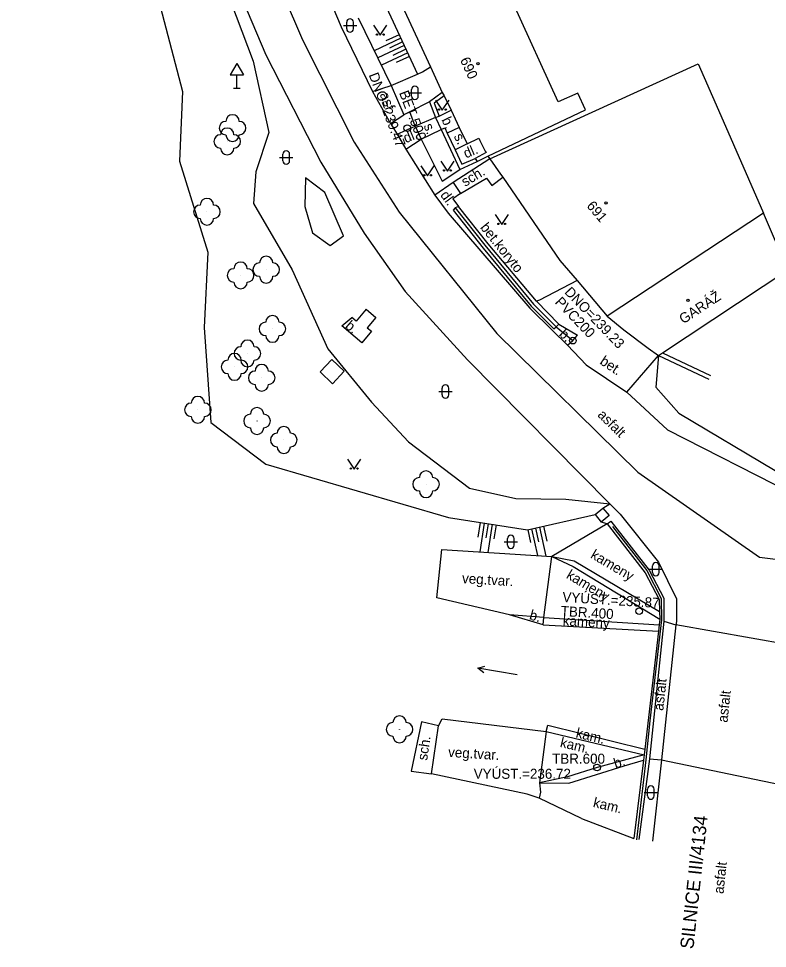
# Model space of a CAD drawing. Extents: x -621335 to -621199, y -1175437 to -1175180.
# Drawn here: x -621295.5 to -621239.4, y -1175437.3 to -1175367.7 of the extents above; entities that cross this region are included whole.
import ezdxf

# ---------------------------------------------------------------- set-up
doc = ezdxf.new("R2010")
doc.units = 0
for name, color, linetype in [('Budovy - měřené', 7, 'Continuous'), ('Budovy - zadní trakty', 7, 'Continuous'), ('Doplňkové značky', 7, 'Continuous'), ('Názvy', 7, 'Continuous'), ('Pomocné popisy', 7, 'Continuous'), ('Rozhraní ploch', 7, 'Continuous'), ('Výškopis', 7, 'Continuous'), ('Zeleň', 7, 'Continuous'), ('Značky druhů budov', 7, 'Continuous'), ('Značky kultur', 7, 'Continuous'), ('Čísla popisná_evidenční', 7, 'Continuous')]:
    doc.layers.add(name, color=color, linetype=linetype)

msp = doc.modelspace()

# ---------------------------------------------------------------- linework, layer by layer
at = {"layer": 'Budovy - měřené'}
for p, q in [((-621251.4, -1175389.96), (-621250.14, -1175390.99)), ((-621248.33, -1175392.36), (-621247.56, -1175392.9))]:
    msp.add_line(p, q, dxfattribs=at)
for points in [[(-621262.49, -1175364.79), (-621266.74, -1175366.77), (-621264.62, -1175371.33)], [(-621263.73, -1175373.23), (-621263.6, -1175373.49), (-621263.08, -1175374.57), (-621262.46, -1175375.85), (-621261.86, -1175377.08), (-621260.99, -1175376.66), (-621260.92, -1175376.82)], [(-621260.52, -1175377.63), (-621260.46, -1175377.74), (-621261.26, -1175378.17), (-621261.13, -1175378.41), (-621260.32, -1175378)], [(-621259.38, -1175379.34), (-621259.21, -1175379.58), (-621254.93, -1175385.81), (-621253.64, -1175387.3), (-621251.4, -1175389.96)]]:
    msp.add_lwpolyline(points, dxfattribs=at)
at = {"layer": 'Budovy - zadní trakty'}
for points in [[(-621260.32, -1175378), (-621253.01, -1175374.55), (-621253.59, -1175373.29), (-621255.05, -1175373.95), (-621258.42, -1175366.56), (-621254.88, -1175364.95), (-621256.13, -1175362.49), (-621257.55, -1175362.98)], [(-621260.17, -1175378.21), (-621244.57, -1175371.1), (-621243.06, -1175374.57), (-621239.7, -1175382.27), (-621251.4, -1175389.96)], [(-621247.56, -1175392.9), (-621247.26, -1175392.7), (-621237.86, -1175386.5), (-621239.7, -1175382.27)]]:
    msp.add_lwpolyline(points, dxfattribs=at)
at = {"layer": 'Doplňkové značky'}
for p, q in [((-621279.11, -1175371.064), (-621279.61, -1175371.93)), ((-621279.11, -1175371.064), (-621278.61, -1175371.93)), ((-621264.62, -1175371.33), (-621263.73, -1175373.23)), ((-621279.61, -1175371.93), (-621278.61, -1175371.93)), ((-621279.11, -1175372.93), (-621279.11, -1175371.93)), ((-621279.36, -1175372.93), (-621278.86, -1175372.93)), ((-621264.25, -1175375.11), (-621265.77, -1175375.75)), ((-621264.25, -1175375.11), (-621263.97, -1175375)), ((-621264.25, -1175375.11), (-621263.82, -1175376.02)), ((-621265.77, -1175375.75), (-621265.31, -1175376.74)), ((-621265.31, -1175376.74), (-621263.82, -1175376.02)), ((-621263.82, -1175376.02), (-621263.55, -1175375.89)), ((-621260.92, -1175376.82), (-621260.52, -1175377.63)), ((-621260.32, -1175378), (-621260.17, -1175378.21)), ((-621260.17, -1175378.21), (-621262.93, -1175379.98)), ((-621260.17, -1175378.21), (-621259.38, -1175379.34)), ((-621262.93, -1175379.98), (-621262.36, -1175380.8)), ((-621250.14, -1175390.99), (-621248.33, -1175392.36)), ((-621247.26, -1175392.7), (-621243.65, -1175394.41)), ((-621247.56, -1175392.9), (-621247.75, -1175395.27)), ((-621247.56, -1175392.9), (-621243.78, -1175394.68)), ((-621265.29, -1175420.31), (-621266.06, -1175424)), ((-621264.01, -1175420.6), (-621265.29, -1175420.31)), ((-621264.54, -1175424.19), (-621264.01, -1175420.6)), ((-621266.06, -1175424), (-621264.54, -1175424.19))]:
    msp.add_line(p, q, dxfattribs=at)
for points in [[(-621267.55, -1175372.72), (-621265.59, -1175371.86), (-621265.22, -1175371.69), (-621264.62, -1175371.33)], [(-621263.73, -1175373.23), (-621264.69, -1175373.95), (-621264.25, -1175375.11)], [(-621264.69, -1175373.95), (-621266.17, -1175374.7), (-621266.6, -1175374.92)], [(-621263.6, -1175373.49), (-621264.33, -1175374.05), (-621263.97, -1175375)], [(-621263.82, -1175376.02), (-621262.42, -1175378.99), (-621261.13, -1175378.41)], [(-621263.55, -1175375.89), (-621263.36, -1175376.28), (-621262.78, -1175377.52), (-621262.27, -1175378.6), (-621261.26, -1175378.17)], [(-621265.31, -1175376.74), (-621263.73, -1175379.88), (-621262.42, -1175378.99)], [(-621262.36, -1175380.8), (-621260.43, -1175379.64), (-621260.03, -1175380.2), (-621259.21, -1175379.58)], [(-621253.64, -1175387.3), (-621256.46, -1175388.77), (-621256.67, -1175388.86)], [(-621251.39, -1175405.51), (-621248.55, -1175409.16), (-621247.51, -1175411.16), (-621247.47, -1175412.05), (-621247.45, -1175412.62), (-621247.5, -1175413.05), (-621247.55, -1175413.54), (-621248.58, -1175422.36), (-621248.63, -1175422.77), (-621248.68, -1175423.17), (-621249.4, -1175429.04)], [(-621251.11, -1175405.3), (-621248.25, -1175408.97), (-621247.16, -1175411.07), (-621247.15, -1175412.79), (-621248.22, -1175423.07), (-621249.01, -1175429.11)], [(-621251, -1175405.71), (-621248.41, -1175408.99), (-621247.36, -1175411.08), (-621247.33, -1175412.67), (-621248.19, -1175420.23), (-621248.49, -1175423.16), (-621249.19, -1175429.13)], [(-621255.54, -1175407.94), (-621253.94, -1175408.7), (-621247.45, -1175412.62)], [(-621248.63, -1175422.77), (-621252.15, -1175423.72), (-621254.36, -1175424.41), (-621256.46, -1175424.88)], [(-621253.31, -1175427.55), (-621256.49, -1175426.01), (-621257.38, -1175425.72), (-621264.54, -1175424.19)]]:
    msp.add_lwpolyline(points, dxfattribs=at)
for centre, radius in [((-621266.351, -1175375.91), 0.25), ((-621266.351, -1175375.91), 0.0005), ((-621253.961, -1175391.8), 0.25), ((-621253.961, -1175391.8), 0.0005), ((-621248.99, -1175412.03), 0.25), ((-621248.99, -1175412.03), 0.0005), ((-621252.15, -1175423.72), 0.25), ((-621252.15, -1175423.72), 0.0005)]:
    msp.add_circle(centre, radius, dxfattribs=at)
at = {"layer": 'Rozhraní ploch'}
for p, q in [((-621268.96, -1175373.16), (-621267.55, -1175372.72)), ((-621268.96, -1175373.16), (-621267.61, -1175375.57)), ((-621267.55, -1175372.72), (-621266.6, -1175374.92)), ((-621263.97, -1175375), (-621263.08, -1175374.57)), ((-621267.61, -1175375.57), (-621266.6, -1175374.92)), ((-621267.61, -1175375.57), (-621267.12, -1175376.35)), ((-621267.12, -1175376.35), (-621265.77, -1175375.75)), ((-621262.46, -1175375.85), (-621263.36, -1175376.28)), ((-621267.12, -1175376.35), (-621266.47, -1175377.49)), ((-621266.47, -1175377.49), (-621265.31, -1175376.74)), ((-621261.86, -1175377.08), (-621262.78, -1175377.52)), ((-621266.47, -1175377.49), (-621264.29, -1175380.91)), ((-621262.93, -1175379.98), (-621264.29, -1175380.91)), ((-621255.02, -1175390.58), (-621253.6, -1175391.4)), ((-621255.49, -1175391.04), (-621254.36, -1175392.15)), ((-621255.2, -1175390.78), (-621253.96, -1175391.8)), ((-621249.92, -1175395.65), (-621247.56, -1175392.9)), ((-621252.29, -1175404.81), (-621251.71, -1175404.33)), ((-621251.71, -1175404.33), (-621251.25, -1175404.89)), ((-621252.29, -1175404.81), (-621251.83, -1175405.37)), ((-621251.25, -1175404.89), (-621251.83, -1175405.37)), ((-621251.39, -1175405.51), (-621255.54, -1175407.94)), ((-621251.39, -1175405.51), (-621251.11, -1175405.3)), ((-621256.12, -1175412.51), (-621255.54, -1175407.94)), ((-621258.69, -1175412.31), (-621264.15, -1175411.04)), ((-621256.17, -1175413.05), (-621258.69, -1175412.31)), ((-621256.12, -1175412.51), (-621258.69, -1175412.31)), ((-621256.17, -1175413.05), (-621256.12, -1175412.51)), ((-621256.12, -1175412.51), (-621247.5, -1175413.05)), ((-621247.15, -1175412.79), (-621246.24, -1175413.05)), ((-621256.17, -1175413.05), (-621247.55, -1175413.54)), ((-621246.24, -1175413.05), (-621247.33, -1175423.15)), ((-621237.16, -1175414.66), (-621246.24, -1175413.05)), ((-621264.01, -1175420.6), (-621263.75, -1175420.09)), ((-621263.75, -1175420.09), (-621255.95, -1175421.04)), ((-621255.95, -1175421.04), (-621255.82, -1175420.55)), ((-621255.82, -1175420.55), (-621248.58, -1175422.36)), ((-621255.95, -1175421.04), (-621256.46, -1175424.88)), ((-621255.95, -1175421.04), (-621248.63, -1175422.77)), ((-621248.22, -1175423.07), (-621247.33, -1175423.15)), ((-621247.33, -1175423.15), (-621238.43, -1175424.99)), ((-621253.31, -1175427.55), (-621249.4, -1175429.04))]:
    msp.add_line(p, q, dxfattribs=at)
for points in [[(-621289.26, -1175328.38), (-621284.69, -1175342.49), (-621282.48, -1175348.71), (-621278.54, -1175359.18), (-621274.2, -1175369.3), (-621270.32, -1175376.95), (-621266.97, -1175382.2), (-621259.66, -1175391.26), (-621249.09, -1175401.63), (-621240, -1175407.99), (-621230.92, -1175409.11)], [(-621275.68, -1175358), (-621271.3, -1175368.33), (-621268.96, -1175373.16)], [(-621281.22, -1175360.35), (-621276.93, -1175370.43), (-621272.83, -1175378.46)], [(-621272.83, -1175378.46), (-621269.57, -1175383.76), (-621266.5, -1175388.12), (-621261.85, -1175393.23), (-621251.2, -1175404)], [(-621264.29, -1175380.91), (-621263.29, -1175382.27), (-621257.18, -1175389.37), (-621255.49, -1175391.04)], [(-621262.36, -1175380.8), (-621262.95, -1175381.19), (-621262.53, -1175381.76)], [(-621262.53, -1175381.76), (-621262.76, -1175381.88), (-621262.92, -1175382.05)], [(-621262.92, -1175382.05), (-621260.67, -1175384.88), (-621257.08, -1175389.22), (-621255.39, -1175390.92)], [(-621262.76, -1175381.88), (-621260.54, -1175384.67), (-621256.9, -1175389.08), (-621255.2, -1175390.78)], [(-621255.02, -1175390.58), (-621256.67, -1175388.86), (-621260.3, -1175384.57), (-621262.53, -1175381.76)], [(-621269.44, -1175389.45), (-621268.71, -1175390.06), (-621269.35, -1175390.83), (-621269.03, -1175391.08), (-621269.75, -1175391.97), (-621271.26, -1175390.69), (-621270.5, -1175390.07)], [(-621269.44, -1175389.45), (-621270.18, -1175390.34), (-621270.5, -1175390.07)], [(-621255.39, -1175390.92), (-621255.2, -1175390.78), (-621255.02, -1175390.58)], [(-621254.36, -1175392.15), (-621253.96, -1175391.8), (-621253.6, -1175391.4)], [(-621254.36, -1175392.15), (-621252.96, -1175393.61), (-621249.92, -1175395.65)], [(-621271.09, -1175394.09), (-621272, -1175393.22), (-621272.88, -1175394.14)], [(-621272.88, -1175394.14), (-621271.95, -1175395.03), (-621271.09, -1175394.09)], [(-621249.92, -1175395.65), (-621246.88, -1175398.47), (-621237.56, -1175403.21), (-621230.15, -1175405.43)], [(-621251.2, -1175404), (-621250.43, -1175404.77), (-621247.54, -1175408.37), (-621246.2, -1175411.11), (-621246.21, -1175412.75), (-621246.226, -1175412.969), (-621246.234, -1175413.051)], [(-621264.15, -1175411.04), (-621263.76, -1175407.43), (-621255.54, -1175407.94)], [(-621255.54, -1175407.94), (-621253.87, -1175408.26), (-621247.47, -1175412.05)], [(-621256.46, -1175424.88), (-621254.27, -1175424.89), (-621250.12, -1175423.6), (-621248.68, -1175423.17)], [(-621247.33, -1175423.15), (-621247.99, -1175429.24)], [(-621256.46, -1175424.88), (-621256.38, -1175425.57), (-621256.49, -1175426.01)]]:
    msp.add_lwpolyline(points, dxfattribs=at)
at = {"layer": 'Výškopis'}
for p, q in [((-621270.02, -1175367.66), (-621267.55, -1175372.72)), ((-621266.956, -1175368.919), (-621267.954, -1175369.383)), ((-621266.83, -1175369.191), (-621268.821, -1175370.116)), ((-621266.577, -1175369.736), (-621268.558, -1175370.656)), ((-621266.703, -1175369.463), (-621267.696, -1175369.925)), ((-621266.324, -1175370.28), (-621268.294, -1175371.195)), ((-621266.451, -1175370.008), (-621267.438, -1175370.466)), ((-621266.198, -1175370.552), (-621267.18, -1175371.008)), ((-621260.896, -1175405.4), (-621261.065, -1175406.493)), ((-621260.599, -1175405.446), (-621260.934, -1175407.605)), ((-621260.303, -1175405.492), (-621260.468, -1175406.558)), ((-621260.006, -1175405.538), (-621260.333, -1175407.643)), ((-621259.71, -1175405.584), (-621259.871, -1175406.623)), ((-621257.338, -1175405.947), (-621257.124, -1175406.901)), ((-621257.046, -1175405.881), (-621256.597, -1175407.874)), ((-621256.753, -1175405.816), (-621256.519, -1175406.855)), ((-621256.46, -1175405.75), (-621255.973, -1175407.913)), ((-621256.168, -1175405.684), (-621255.914, -1175406.808)), ((-621251.39, -1175405.51), (-621251.83, -1175405.37))]:
    msp.add_line(p, q, dxfattribs=at)
for points in [[(-621295.45, -1175349.87), (-621290.21, -1175351.04), (-621287.51, -1175351.48), (-621286.52, -1175352.52), (-621286.18, -1175357.56), (-621285.26, -1175365.24), (-621283.18, -1175373.16), (-621283.4, -1175378.38)], [(-621268.17, -1175366.18), (-621268.08, -1175366.5), (-621265.59, -1175371.86)], [(-621283.4, -1175378.38), (-621281.29, -1175385.19), (-621281.56, -1175390.81), (-621281.06, -1175397.92), (-621276.95, -1175401.05), (-621263.28, -1175405.03), (-621257.35, -1175405.95), (-621252.29, -1175404.81)]]:
    msp.add_lwpolyline(points, dxfattribs=at)
at = {"layer": 'Zeleň'}
for p, q in [((-621265.77, -1175375.75), (-621266.17, -1175374.7)), ((-621251.71, -1175404.33), (-621251.2, -1175404))]:
    msp.add_line(p, q, dxfattribs=at)
for points in [[(-621281.79, -1175360.58), (-621277.88, -1175370.89), (-621276.71, -1175376.23)], [(-621276.71, -1175376.23), (-621277.69, -1175379.17), (-621277.86, -1175381.54), (-621274.98, -1175386.51), (-621272.3, -1175392.41), (-621269.04, -1175396.39), (-621266.25, -1175399.37), (-621261.69, -1175402.83), (-621258.22, -1175403.61), (-621254.48, -1175403.65), (-621251.2, -1175404)], [(-621273.97, -1175379.62), (-621274.02, -1175381.76), (-621273.45, -1175383.74), (-621272.13, -1175384.68), (-621271.12, -1175383.95), (-621272.52, -1175380.73), (-621273.97, -1175379.62)], [(-621247.75, -1175395.27), (-621246.03, -1175397.22), (-621238.82, -1175401.51)]]:
    msp.add_lwpolyline(points, dxfattribs=at)
for centre in [(-621279.43, -1175375.9), (-621279.83, -1175376.9), (-621281.35, -1175382.16), (-621276.91, -1175386.49), (-621278.83, -1175386.92), (-621276.45, -1175390.92), (-621278.32, -1175392.76), (-621279.28, -1175393.76), (-621277.25, -1175394.58), (-621282.03, -1175396.97), (-621277.6, -1175397.81), (-621275.6, -1175399.23), (-621264.95, -1175402.54), (-621266.93, -1175420.87)]:
    msp.add_circle(centre, 0.0005, dxfattribs=at)
for centre, start, end in [((-621279.43, -1175375.4), 0, 179.99999), ((-621279.93, -1175375.9), 89.99999, 269.99999), ((-621279.83, -1175376.4), 0, 179.99999), ((-621278.93, -1175375.9), 270, 89.99999), ((-621280.33, -1175376.9), 89.99999, 269.99999), ((-621279.43, -1175376.4), 179.99999, 359.99999), ((-621279.33, -1175376.9), 270, 89.99999), ((-621279.83, -1175377.4), 179.99999, 359.99999), ((-621281.35, -1175381.66), 0, 179.99999), ((-621281.85, -1175382.16), 89.99999, 269.99999), ((-621280.85, -1175382.16), 270, 89.99999), ((-621281.35, -1175382.66), 179.99999, 359.99999), ((-621276.91, -1175385.99), 0, 179.99999), ((-621279.33, -1175386.92), 89.99999, 269.99999), ((-621278.83, -1175386.42), 0, 179.99999), ((-621278.33, -1175386.92), 270, 89.99999), ((-621277.41, -1175386.49), 89.99999, 269.99999), ((-621276.41, -1175386.49), 270, 89.99999), ((-621276.91, -1175386.99), 179.99999, 359.99999), ((-621278.83, -1175387.42), 179.99999, 359.99999), ((-621276.45, -1175390.42), 0, 179.99999), ((-621276.95, -1175390.92), 89.99999, 269.99999), ((-621275.95, -1175390.92), 270, 89.99999), ((-621278.32, -1175392.26), 0, 179.99999), ((-621276.45, -1175391.42), 179.99999, 359.99999), ((-621279.28, -1175393.26), 0, 179.99999), ((-621278.82, -1175392.76), 89.99999, 269.99999), ((-621277.82, -1175392.76), 270, 89.99999), ((-621279.78, -1175393.76), 89.99999, 269.99999), ((-621278.32, -1175393.26), 179.99999, 359.99999), ((-621278.78, -1175393.76), 270, 89.99999), ((-621277.75, -1175394.58), 89.99999, 269.99999), ((-621277.25, -1175394.08), 0, 179.99999), ((-621276.75, -1175394.58), 270, 89.99999), ((-621279.28, -1175394.26), 179.99999, 359.99999), ((-621277.25, -1175395.08), 179.99999, 359.99999), ((-621282.03, -1175396.47), 0, 179.99999), ((-621282.53, -1175396.97), 89.99999, 269.99999), ((-621281.53, -1175396.97), 270, 89.99999), ((-621277.6, -1175397.31), 0, 179.99999), ((-621282.03, -1175397.47), 179.99999, 359.99999), ((-621278.1, -1175397.81), 89.99999, 269.99999), ((-621277.1, -1175397.81), 270, 89.99999), ((-621277.6, -1175398.31), 179.99999, 359.99999), ((-621275.6, -1175398.73), 0, 179.99999), ((-621276.1, -1175399.23), 89.99999, 269.99999), ((-621275.1, -1175399.23), 270, 89.99999), ((-621275.6, -1175399.73), 179.99999, 359.99999), ((-621264.95, -1175402.04), 0, 179.99999), ((-621265.45, -1175402.54), 89.99999, 269.99999), ((-621264.45, -1175402.54), 270, 89.99999), ((-621264.95, -1175403.04), 179.99999, 359.99999), ((-621266.93, -1175420.37), 0, 179.99999), ((-621267.43, -1175420.87), 89.99999, 269.99999), ((-621266.43, -1175420.87), 270, 89.99999), ((-621266.93, -1175421.37), 179.99999, 359.99999)]:
    msp.add_arc(centre, 0.5, start, end, dxfattribs=at)
at = {"layer": 'Značky druhů budov'}
for centre in [(-621261.06, -1175371.08), (-621251.47, -1175381.5), (-621245.35, -1175388.79)]:
    msp.add_circle(centre, 0.0875, dxfattribs=at)
at = {"layer": 'Značky kultur'}
for p, q in [((-621271.14, -1175368.23), (-621270.14, -1175368.23)), ((-621270.89, -1175368.48), (-621270.89, -1175367.98)), ((-621270.39, -1175368.48), (-621270.39, -1175367.98)), ((-621266.28, -1175373.27), (-621265.28, -1175373.27)), ((-621266.03, -1175373.52), (-621266.03, -1175373.02)), ((-621265.53, -1175373.52), (-621265.53, -1175373.02)), ((-621275.91, -1175378.1), (-621274.91, -1175378.1)), ((-621275.66, -1175378.35), (-621275.66, -1175377.85)), ((-621275.16, -1175378.35), (-621275.16, -1175377.85)), ((-621263.75, -1175395.85), (-621263.75, -1175395.35)), ((-621263.25, -1175395.85), (-621263.25, -1175395.35)), ((-621264, -1175395.6), (-621263, -1175395.6)), ((-621258.857, -1175407.097), (-621258.857, -1175406.597)), ((-621258.357, -1175407.097), (-621258.357, -1175406.597)), ((-621259.107, -1175406.847), (-621258.107, -1175406.847)), ((-621248, -1175409.14), (-621248, -1175408.64)), ((-621247.5, -1175409.14), (-621247.5, -1175408.64)), ((-621248.25, -1175408.89), (-621247.25, -1175408.89)), ((-621258.12, -1175416.797), (-621261.08, -1175416.303)), ((-621248.37, -1175425.85), (-621248.37, -1175425.35)), ((-621247.87, -1175425.85), (-621247.87, -1175425.35)), ((-621248.62, -1175425.6), (-621247.62, -1175425.6))]:
    msp.add_line(p, q, dxfattribs=at)
for points in [[(-621268.88, -1175368.21), (-621268.38, -1175368.96), (-621267.88, -1175368.21)], [(-621264.23, -1175373.82), (-621263.73, -1175374.57), (-621263.23, -1175373.82)], [(-621265.33, -1175378.73), (-621264.83, -1175379.48), (-621264.33, -1175378.73)], [(-621263.85, -1175378.37), (-621263.35, -1175379.12), (-621262.85, -1175378.37)], [(-621259.78, -1175382.37), (-621259.28, -1175383.12), (-621258.78, -1175382.37)], [(-621270.83, -1175400.67), (-621270.33, -1175401.42), (-621269.83, -1175400.67)], [(-621260.628, -1175416.632), (-621261.08, -1175416.303), (-621260.545, -1175416.139)]]:
    msp.add_lwpolyline(points, dxfattribs=at)
for centre in [(-621268.63, -1175368.91), (-621268.13, -1175368.91), (-621263.98, -1175374.52), (-621263.48, -1175374.52), (-621265.08, -1175379.43), (-621264.58, -1175379.43), (-621263.6, -1175379.07), (-621263.1, -1175379.07), (-621259.53, -1175383.07), (-621259.03, -1175383.07), (-621270.58, -1175401.37), (-621270.08, -1175401.37)]:
    msp.add_circle(centre, 0.05, dxfattribs=at)
for centre, start, end in [((-621270.64, -1175367.98), 0, 179.99999), ((-621270.64, -1175368.48), 179.99999, 359.99999), ((-621265.78, -1175373.02), 0, 179.99999), ((-621265.78, -1175373.52), 179.99999, 359.99999), ((-621275.41, -1175377.85), 0, 179.99999), ((-621275.41, -1175378.35), 179.99999, 359.99999), ((-621263.5, -1175395.35), 0, 179.99999), ((-621263.5, -1175395.85), 179.99999, 359.99999), ((-621258.607, -1175406.597), 0, 179.99999), ((-621258.607, -1175407.097), 179.99999, 359.99999), ((-621247.75, -1175408.64), 0, 179.99999), ((-621247.75, -1175409.14), 179.99999, 359.99999), ((-621248.12, -1175425.35), 0, 179.99999), ((-621248.12, -1175425.85), 179.99999, 359.99999)]:
    msp.add_arc(centre, 0.25, start, end, dxfattribs=at)

# ---------------------------------------------------------------- texts
at = {"layer": 'Názvy'}
msp.add_text('SILNICE III/4134', height=1, rotation=83.83911, dxfattribs=at).set_placement((-621244.94, -1175437.34))
at = {"layer": 'Pomocné popisy'}
for s, rotation, p in [('DNO=239.47', 290.85, (-621269.25, -1175371.92)), ('asf.', 291.42529, (-621268.43, -1175373.38)), ('BET.500', 290.85, (-621266.98, -1175373.26)), ('b.', 295.29202, (-621263.81, -1175375.28)), ('dl.', 22.83, (-621266.46, -1175377.04)), ('s.', 292.83, (-621265.15, -1175375.73)), ('s.', 296.00335, (-621262.89, -1175376.51)), ('dl.', 22.76112, (-621261.96, -1175378.18)), ('sch.', 31.00739, (-621262.03, -1175380.31)), ('dl.', 306.32683, (-621263.92, -1175380.92)), ('bet.koryto', 308.48656, (-621260.93, -1175383.35)), ('DNO=239.23', 313.81, (-621254.631, -1175388.214)), ('PVC200', 313.81, (-621255.347, -1175388.963)), ('GARÁŽ', 33.31552, (-621245.69, -1175390.58)), ('b.', 319.71, (-621271.06, -1175390.79)), ('b.', 315.51156, (-621255.04, -1175391.37)), ('bet.', 326.13631, (-621252, -1175393.5)), ('asfalt', 315.54722, (-621252.16, -1175397.41)), ('kameny', 329.36651, (-621252.69, -1175408.01)), ('veg.tvar.', 356.4497, (-621262.27, -1175409.93)), ('kameny', 329.36651, (-621254.508, -1175409.523)), ('VYÚST.=235.87', 356.41539, (-621254.76, -1175411.34)), ('b.', 343.64, (-621257.27, -1175412.63)), ('TBR.400', 356.41539, (-621254.883, -1175412.384)), ('kameny', 356.74655, (-621254.73, -1175413.1)), ('asfalt', 83.84, (-621247.19, -1175419.5)), ('asfalt', 83.84, (-621242.39, -1175420.39)), ('kam.', 346.70278, (-621253.78, -1175421.47)), ('sch.', 81.60195, (-621264.87, -1175423.23)), ('kam.', 346.70278, (-621254.961, -1175422.177)), ('veg.tvar.', 356.4497, (-621263.311, -1175422.93)), ('b.', 17.26751, (-621250.77, -1175423.8)), ('kam.', 346.70278, (-621252.49, -1175426.665)), ('asfalt', 83.84, (-621242.689, -1175433.2))]:
    msp.add_text(s, height=0.75, rotation=rotation, dxfattribs=at).set_placement(p)
for s, p in [('TBR.600', (-621255.51, -1175423.44)), ('VYÚST.=236.72', (-621261.38, -1175424.57))]:
    msp.add_text(s, height=0.75, dxfattribs=at).set_placement(p)
at = {"layer": 'Čísla popisná_evidenční'}
for s, rotation, p in [('690', 294.51, (-621262.42, -1175370.8)), ('691', 310.10091, (-621252.97, -1175381.74))]:
    msp.add_text(s, height=0.75, rotation=rotation, dxfattribs=at).set_placement(p)

doc.saveas('drawing.dxf')
